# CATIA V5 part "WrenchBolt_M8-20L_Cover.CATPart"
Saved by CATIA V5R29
Part number: WrenchBolt_M8-20L_Cover
Source: Unknown
Bounding box of the stored display mesh (mm): x -6.635 to 6.635, y -6.635 to 6.625, z -20 to 8
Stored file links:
  C:\가치같이\SmartFactory_BoxErectorConveyor\Boxing(under)\WrenchBolt_M8-20L_Cover.CATPart
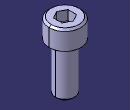
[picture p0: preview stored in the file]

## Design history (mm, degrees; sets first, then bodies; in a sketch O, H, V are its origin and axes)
Body1 (main body)
  Solid1 "PartBody": solid without history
